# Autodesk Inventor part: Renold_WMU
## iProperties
Author: Administrator
Shininess: 33.0
Angle Display Precision: 2
Document Length Units: 11272
Document Angle Units: 11286
Document Time Units: 11279
Document Mass Units: 11290
Document Length Units Precision: 3
Document Angle Units Precision: 2
Compacted: True
PropertySet Name: _Private Model Information
Created: 2002-04
Part Number: Renold_WMU
Material: ASTM A36 HRS
Document SubType Name: Modeling
Designer: Administrator
Control State: 0
Master: False
Checked Out: False
PropertySet Name: Design Tracking Control
Density: 0.0
Volumn: 0.0
Area: 0.0
PropertySet Name: Model Information
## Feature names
1. body_from_top [Extrusion]
2. bolt_down_holes [Hole]
3. Fillet1
4. cutout_from_center [Extrusion]
5. Fillet2
6. input_pad [Extrusion]
7. top_bottom_cutout [Extrusion]
8. output_pad [Extrusion]
9. Chamfer1
10. shield_bolt_holes [Extrusion]
11. long_rib [Extrusion]
12. Rectangular Pattern1
13. short_rib [Extrusion]
14. Rectangular Pattern2
15. Hole2
16. oil_boss [Extrusion]
17. pipe_plug [Extrusion]
18. hex_in [Extrusion]
19. side_fill [Extrusion]
20. side_fill_plug [Extrusion]
21. side_fill_hex [Extrusion]
22. Mirror3
23. top_fill [Extrusion]
24. top_fill_plug [Extrusion]
25. top_fill_plug_hex [Extrusion]
26. bottom_fill [Extrusion]
27. bottom_filll_plug [Extrusion]
28. bottom_fill_plug_hex [Extrusion]
29. mirror_ouputpad_ribs
30. input_shaft [Revolution]
31. input_keyway [Extrusion]
32. end_of_input_chamf [Chamfer]
33. mirrored_inputshaft
34. output_shaft [Revolution]
35. keyway_on_output_shaft [Extrusion]
36. output_shaft_hole [Revolution]
37. shaft_hole_keyway [Extrusion]
